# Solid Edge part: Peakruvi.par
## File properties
Author: Olev
Template: Normal.par
Last saved by: Olev
Revision: 14
Application: Solid Edge
Accuracy: 0,990
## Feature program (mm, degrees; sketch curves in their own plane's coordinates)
sketch for "unnamed Protrusion 1" plane through (0, 0, 0) normal (0, -1, 0) x-axis (1, 0, 0)
  circle centre (0, 0) radius 1.25
extrude "unnamed Protrusion 1" add finite 2.5 symmetric
swept protrusion "unnamed SweptProtrusion 1"
sketch for "ExtrudedCutout_1" plane through (0, 0, 0) normal (0, -1, 0) x-axis (1, 0, 0)
  bspline degree 3 poles (-1.7819, 5.0236) (-1.9854, 5.4374) (-2.1041, 5.6309) (-2.5015, 6.9485) (-1.438, 8.2725) (0.6239, 9.315) (1.211, 7.9369) (1.3619, 7.2111) knots 0 0.1393 0.1813 0.565 0.7055 1 multiplicities 4 1 1 1 1 4
  line (1.8876, 7.7209) -> (1.3619, 7.2111)
  line (0.8762, 10.0675) -> (1.8876, 7.7209)
  line (-3.8044, 6.7902) -> (0.8762, 10.0675)
  line (-2.8855, 5.6155) -> (-3.8044, 6.7902)
  line (-1.7819, 5.0236) -> (-2.8855, 5.6155)
extrude "ExtrudedCutout_1" cut finite 15.8263 symmetric
pattern "unnamed Pattern 1" of "ExtrudedCutout_1", "unnamed SweptProtrusion 1"
pattern "unnamed Pattern 2"
chamfer "Chamfer_3" setback 0.05
sketch for "ExtrudedCutout_2" plane through (0, 1.25, 0) normal (0, 1, 0) x-axis (0, 0, 1)
extrude "ExtrudedCutout_2" cut finite 3.042 along -normal
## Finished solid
Body 1: solid body, 31 faces, 66 edges, 40 vertices.
  Faces by surface: spline 10, swept 10, plane 7, cone 2, cylinder 2
  Edges by curve: intersection 30, curve on surface 10, line 10, spline 10, circle 6
Bounding box of the edges (mm; curved faces can reach further): 17.043 x 2.500 x 16.347, from (-8.4866, -1.25, -7.4278) to (8.5566, 1.25, 8.9192).
Cylindrical faces by radius (mm): R0.85 x1, R1.25 x1
Conical faces (half-angle, radius in mm at the cone's reference point): 45 deg R1.2 x1, 45 deg R1.25 x1
Planar faces by outward normal: +y 1, -y 1, oblique 5
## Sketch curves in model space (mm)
line (0.3793, 0.3049, 9.4075) -> (0.4278, 0.3109, 9.443)
spline (0.3793, 0.3049, 9.4075) -> (-3.1356, -0.2984, 6.8293) -> (0.4278, 0.3109, 9.443)
spline (0, 0, 0) -> (-0.1643, 0, 3.9863) -> (-1.6915, 0, 7.8886)
line (0.5524, 1.0774, 0) -> (0.5793, 1.1029, 0)
spline (0.5793, 1.1029, 0) -> (-0.3859, -0.6395, 0) -> (0.5524, 1.0774, 0)
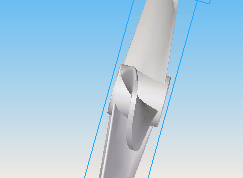
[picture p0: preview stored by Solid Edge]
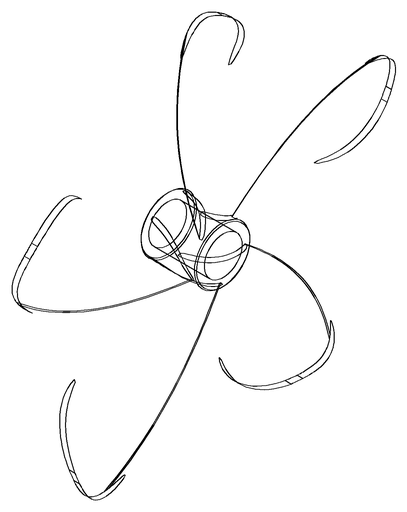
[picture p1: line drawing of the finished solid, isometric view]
